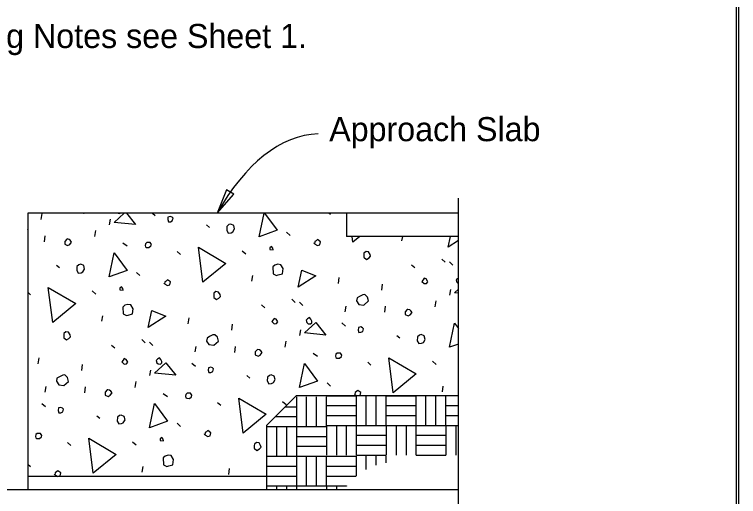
# Model space of a CAD drawing. Extents: x 0 to 30.8, y 0 to 21.2.
# Drawn here: x 26.255 to 30.8, y 6.756 to 9.783 of the extents above; entities that cross this region are included whole.
import ezdxf

# ---------------------------------------------------------------- set-up
doc = ezdxf.new("R2010")
doc.units = 0
for name, color, linetype in [('ActivePts-ConstElements', 7, 'Continuous'), ('Dimension', 7, 'Continuous'), ('Lighting', 7, 'Continuous'), ('Miscellaneous', 7, 'Continuous'), ('Miscellaneous1', 7, 'Continuous'), ('SupstrConc', 7, 'Continuous'), ('TextStructures', 7, 'Continuous')]:
    doc.layers.add(name, color=color, linetype=linetype)

msp = doc.modelspace()

# ---------------------------------------------------------------- linework, layer by layer
at = {"layer": 'ActivePts-ConstElements'}
msp.add_lwpolyline([(0, 0), (30.7879, 0), (30.7879, 19.4596), (0, 19.4596)], close=True, dxfattribs=at)
at = {"layer": 'Dimension'}
msp.add_lwpolyline([(27.5267, 8.5352), (27.6314, 8.6541), (27.5864, 8.682)], close=True, dxfattribs=at)
msp.add_lwpolyline([(29.0415, 6.3424), (29.0415, 8.629)], dxfattribs=at)
msp.add_ellipse((28.2718, 6.6665), major_axis=(0.1111, -2.3674), ratio=0.464296, start_param=3.141604, end_param=3.781059, dxfattribs=at)
at = {"layer": 'Lighting'}
msp.add_line((29.0415, 6.7981), (25.9826, 6.7981), dxfattribs=at)
at = {"layer": 'Miscellaneous'}
for p, q in [((26.4229, 8.4948), (26.4283, 8.5325)), ((27.1206, 8.5353), (27.138, 8.5207)), ((28.2306, 8.5353), (28.2385, 8.5283)), ((29.0415, 8.5353), (28.338, 8.5353)), ((26.8509, 8.4619), (26.857, 8.4972)), ((27.4592, 8.4619), (27.4789, 8.4464)), ((26.7594, 8.3882), (26.7648, 8.4259)), ((27.9633, 8.4158), (27.9843, 8.3955)), ((26.4422, 8.355), (26.4476, 8.3927)), ((28.6871, 8.3612), (28.692, 8.3895)), ((26.9353, 8.35), (26.9611, 8.331)), ((27.2765, 8.2938), (27.2968, 8.276)), ((27.6839, 8.2995), (27.7072, 8.2799)), ((28.9376, 8.2472), (28.9586, 8.2269)), ((28.9864, 8.2292), (29.0074, 8.209)), ((26.5174, 8.2095), (26.5371, 8.1941)), ((28.7478, 8.2119), (28.7681, 8.194)), ((27.0215, 8.1634), (27.0425, 8.1432)), ((27.7453, 8.1089), (27.7514, 8.1442)), ((28.2877, 8.0938), (28.2931, 8.1314)), ((26.7421, 8.0471), (26.7655, 8.0275)), ((28.5601, 8.0529), (28.5655, 8.0905)), ((28.9881, 8.02), (28.9942, 8.0553)), ((26.338, 8.0386), (26.355, 8.0236)), ((27.806, 7.9595), (27.8263, 7.9417)), ((27.9959, 7.9948), (28.0168, 7.9746)), ((28.0447, 7.9769), (28.0656, 7.9566)), ((28.8966, 7.9463), (28.902, 7.984)), ((28.3301, 7.9162), (28.3362, 7.9515)), ((28.5794, 7.9131), (28.5848, 7.9508)), ((26.8035, 7.8565), (26.8096, 7.8918)), ((27.3459, 7.8414), (27.3513, 7.8791)), ((27.6183, 7.8005), (27.6237, 7.8382)), ((28.3101, 7.8461), (28.3334, 7.8265)), ((28.0464, 7.7677), (28.0524, 7.803)), ((27.0541, 7.7425), (27.075, 7.7222)), ((27.9548, 7.694), (27.9603, 7.7317)), ((28.6546, 7.7676), (28.6743, 7.7522)), ((26.8642, 7.7072), (26.8846, 7.6893)), ((27.1029, 7.7245), (27.1238, 7.7043)), ((27.3883, 7.6638), (27.3944, 7.6991)), ((27.6376, 7.6607), (27.643, 7.6984)), ((28.1307, 7.6557), (28.1565, 7.6367)), ((26.4041, 7.5891), (26.4096, 7.6267)), ((27.3683, 7.5938), (27.3917, 7.5741)), ((28.4719, 7.5996), (28.4922, 7.5817)), ((28.8793, 7.6052), (28.9027, 7.5856)), ((26.6765, 7.5482), (26.6819, 7.5858)), ((27.1046, 7.5153), (27.1107, 7.5506)), ((27.7128, 7.5153), (27.7325, 7.4998)), ((27.013, 7.4416), (27.0185, 7.4793)), ((28.2169, 7.4692), (28.2379, 7.4489)), ((26.4465, 7.4115), (26.4526, 7.4468)), ((26.6958, 7.4084), (26.7013, 7.4461)), ((28.9407, 7.4146), (28.9468, 7.4499)), ((27.1889, 7.4034), (27.2147, 7.3844)), ((28.0267, 7.0091), (28.0267, 7.3829)), ((28.088, 7.1966), (28.088, 7.3829)), ((28.1505, 7.1966), (28.1505, 7.3829)), ((28.2128, 7.3895), (28.4016, 7.3895)), ((28.213, 7.1966), (28.213, 7.3829)), ((28.4016, 7.0157), (28.4016, 7.3895)), ((28.4628, 7.2032), (28.4628, 7.3895)), ((28.5253, 7.2032), (28.5253, 7.3895)), ((28.5878, 7.3895), (28.7766, 7.3895)), ((28.5878, 7.2032), (28.5878, 7.3895)), ((28.7766, 7.0157), (28.7766, 7.3895)), ((28.8378, 7.2032), (28.8378, 7.3895)), ((28.9003, 7.2032), (28.9003, 7.3895)), ((28.9628, 7.2032), (28.9628, 7.3895)), ((26.4265, 7.3414), (26.4499, 7.3218)), ((27.5301, 7.3472), (27.5504, 7.3294)), ((27.9375, 7.3529), (27.9609, 7.3333)), ((27.9535, 7.3204), (28.0267, 7.3204)), ((28.2128, 7.327), (28.4016, 7.327)), ((28.5878, 7.327), (28.7766, 7.327)), ((28.9628, 7.327), (29.0415, 7.327)), ((26.7711, 7.2629), (26.7907, 7.2475)), ((27.891, 7.2579), (28.0267, 7.2579)), ((28.2128, 7.2645), (28.4016, 7.2645)), ((28.5878, 7.2645), (28.7766, 7.2645)), ((28.9628, 7.2645), (29.0415, 7.2645)), ((27.2752, 7.2168), (27.2961, 7.1965)), ((27.838, 7.1966), (28.213, 7.1966)), ((27.9005, 7.1966), (27.9005, 7.0091)), ((27.963, 7.1966), (27.963, 7.0091)), ((28.2128, 7.2032), (28.5878, 7.2032)), ((28.2128, 7.2032), (28.2128, 7.0157)), ((28.2753, 7.2032), (28.2753, 7.0157)), ((28.3378, 7.2032), (28.3378, 7.0157)), ((28.5878, 7.2032), (28.9628, 7.2032)), ((28.5878, 7.2032), (28.5878, 7.0157)), ((28.6503, 7.2032), (28.6503, 7.0157)), ((28.7128, 7.2032), (28.7128, 7.0157)), ((28.9628, 7.2033), (29.0415, 7.2033)), ((28.9628, 7.2032), (28.9628, 7.0157)), ((29.0253, 7.2032), (29.0253, 7.0157)), ((28.4016, 7.1407), (28.5878, 7.1407)), ((28.7766, 7.1407), (28.9628, 7.1407)), ((26.5883, 7.0949), (26.6086, 7.077)), ((26.9957, 7.1005), (27.0191, 7.0809)), ((28.0267, 7.1341), (28.213, 7.1341)), ((28.0267, 7.0716), (28.213, 7.0716)), ((28.4016, 7.0782), (28.5878, 7.0782)), ((28.7766, 7.0782), (28.9628, 7.0782)), ((27.838, 7.0091), (28.0267, 7.0091)), ((28.0267, 7.0091), (28.213, 7.0091)), ((28.0267, 6.7981), (28.0267, 7.0091)), ((28.088, 6.8229), (28.088, 7.0091)), ((28.1505, 6.8229), (28.1505, 7.0091)), ((28.213, 7.0091), (28.4017, 7.0091)), ((28.213, 6.8229), (28.213, 7.0091)), ((28.4016, 7.0157), (28.5878, 7.0157)), ((28.4017, 6.8863), (28.4017, 7.0092)), ((28.463, 6.9264), (28.463, 7.0092)), ((28.5255, 6.9529), (28.5255, 7.0092)), ((28.588, 6.9669), (28.588, 7.0092)), ((28.7766, 7.0157), (28.9628, 7.0157)), ((26.338, 6.96), (26.3543, 6.9442)), ((27.0572, 6.9099), (27.0632, 6.9452)), ((27.5996, 6.8948), (27.605, 6.9325)), ((27.838, 6.9466), (28.0267, 6.9466)), ((28.213, 6.9466), (28.4017, 6.9466)), ((27.838, 6.8814), (26.338, 6.8814)), ((27.838, 6.8841), (28.0267, 6.8841)), ((28.213, 6.8842), (28.3991, 6.8842)), ((27.838, 6.8229), (28.213, 6.8229)), ((27.9005, 6.8229), (27.9005, 6.7981)), ((27.963, 6.8229), (27.963, 6.7981)), ((28.213, 6.8229), (28.3388, 6.8229)), ((28.213, 6.8229), (28.213, 6.7981)), ((28.2755, 6.8229), (28.2755, 6.7981)), ((28.338, 6.8229), (28.338, 6.8219))]:
    msp.add_line(p, q, dxfattribs=at)
for points in [[(26.6887, 8.5353), (26.689, 8.535), (26.6923, 8.5353)], [(26.8804, 8.4776), (26.9425, 8.5353)], [(26.957, 8.5353), (27.0134, 8.4641), (26.8804, 8.4776)], [(26.9059, 8.5353), (26.917, 8.534), (26.9186, 8.5353)], [(27.2173, 8.4954), (27.2212, 8.4809), (27.2339, 8.4817), (27.2453, 8.4874), (27.2511, 8.5045), (27.2443, 8.5104), (27.2327, 8.5151), (27.2182, 8.5112), (27.2173, 8.4954)], [(27.7897, 8.3874), (27.8211, 8.5353)], [(27.824, 8.5353), (27.9031, 8.4281), (27.7897, 8.3874)], [(27.5885, 8.4525), (27.5871, 8.4288), (27.5971, 8.4108), (27.6147, 8.4129), (27.6261, 8.4186), (27.6367, 8.437), (27.6309, 8.4587), (27.6131, 8.4669), (27.6011, 8.4636), (27.5885, 8.4525)], [(26.338, 8.424), (26.3403, 8.4261), (26.338, 8.4349)], [(26.5707, 8.3584), (26.5704, 8.3402), (26.5881, 8.332), (26.602, 8.3383), (26.6132, 8.3542), (26.6052, 8.365), (26.5984, 8.371), (26.5874, 8.3732), (26.5826, 8.3719), (26.5707, 8.3584)], [(28.138, 8.3435), (28.1563, 8.3329), (28.1708, 8.3368), (28.1759, 8.3563), (28.1569, 8.3693), (28.1486, 8.3619), (28.1395, 8.3569), (28.138, 8.3435), (28.1367, 8.3483)], [(28.3785, 8.3536), (28.374, 8.3895)], [(28.4221, 8.3895), (28.3785, 8.3536)], [(28.977, 8.3225), (28.9914, 8.3895)], [(29.0415, 8.3639), (28.977, 8.3225)], [(27.0771, 8.3232), (27.0832, 8.3197), (27.099, 8.3188), (27.1115, 8.3299), (27.1144, 8.3384), (27.1057, 8.3516), (27.0851, 8.3513), (27.0767, 8.3438), (27.0745, 8.3329), (27.0771, 8.3232)], [(27.4368, 8.1013), (27.4088, 8.3215), (27.5809, 8.2201), (27.4368, 8.1013)], [(27.8578, 8.3073), (27.879, 8.3052), (27.8765, 8.3149), (27.8684, 8.3256), (27.8576, 8.3176), (27.8578, 8.3073)], [(26.848, 8.135), (26.88, 8.286), (26.9613, 8.1757), (26.848, 8.135)], [(28.4484, 8.2766), (28.4481, 8.2584), (28.4647, 8.2447), (28.4803, 8.2541), (28.4904, 8.2645), (28.4872, 8.2766), (28.4778, 8.2922), (28.4614, 8.2956), (28.4488, 8.2845), (28.4484, 8.2766)], [(26.6467, 8.2002), (26.6453, 8.1765), (26.6553, 8.1585), (26.6729, 8.1606), (26.6843, 8.1662), (26.6949, 8.1846), (26.6891, 8.2063), (26.6714, 8.2145), (26.6593, 8.2113), (26.6467, 8.2002)], [(27.8766, 8.1984), (27.8779, 8.1548), (27.8987, 8.1448), (27.9108, 8.1481), (27.9374, 8.1552), (27.9417, 8.1874), (27.9273, 8.212), (27.9085, 8.2147), (27.8891, 8.2095), (27.8766, 8.1984)], [(28.0352, 8.0701), (28.0583, 8.1772), (28.1456, 8.1411), (28.0352, 8.0701)], [(27.1962, 8.0912), (27.2145, 8.0806), (27.229, 8.0844), (27.2342, 8.1039), (27.2151, 8.1169), (27.2068, 8.1095), (27.1978, 8.1045), (27.1962, 8.0912), (27.1949, 8.096)], [(28.812, 8.1074), (28.8262, 8.0931), (28.8413, 8.0946), (28.8491, 8.1044), (28.8478, 8.1092), (28.8391, 8.1224), (28.8275, 8.1271), (28.8197, 8.1173), (28.812, 8.1074)], [(29.0415, 8.1272), (29.0355, 8.1233), (29.0272, 8.1159), (29.031, 8.1014)], [(29.031, 8.1014), (29.0409, 8.0937), (29.0415, 8.0936)], [(26.495, 7.8489), (26.467, 8.0692), (26.6391, 7.9678), (26.495, 7.8489)], [(26.916, 8.0549), (26.9373, 8.0528), (26.9347, 8.0625), (26.9266, 8.0733), (26.9158, 8.0652), (26.916, 8.0549)], [(29.0176, 8.0357), (29.0415, 8.0579)], [(27.5066, 8.0242), (27.5063, 8.006), (27.5229, 7.9924), (27.5385, 8.0017), (27.5486, 8.0122), (27.5454, 8.0243), (27.536, 8.0399), (27.5196, 8.0432), (27.5071, 8.0321), (27.5066, 8.0242)], [(28.4023, 7.9847), (28.416, 7.9625), (28.4483, 7.9582), (28.4775, 7.9842), (28.4711, 8.0083), (28.4538, 8.0244), (28.4411, 8.0236), (28.4207, 8.0129), (28.405, 8.0036), (28.4023, 7.9847)], [(29.0415, 8.0333), (29.0176, 8.0357)], [(26.9348, 7.9461), (26.9362, 7.9024), (26.9569, 7.8925), (26.969, 7.8957), (26.9956, 7.9028), (26.9999, 7.935), (26.9855, 7.9597), (26.9667, 7.9624), (26.9474, 7.9572), (26.9348, 7.9461)], [(27.0934, 7.8178), (27.1165, 7.9249), (27.2038, 7.8887), (27.0934, 7.8178)], [(28.7079, 7.9165), (28.7076, 7.8983), (28.7253, 7.8901), (28.7392, 7.8964), (28.7504, 7.9123), (28.7424, 7.9231), (28.7356, 7.9291), (28.7246, 7.9313), (28.7198, 7.93), (28.7079, 7.9165)], [(27.8702, 7.8551), (27.8844, 7.8408), (27.8996, 7.8422), (27.9073, 7.8521), (27.906, 7.8569), (27.8973, 7.8701), (27.8857, 7.8747), (27.878, 7.8649), (27.8702, 7.8551)], [(28.0893, 7.8491), (28.0991, 7.8413), (28.1125, 7.8397), (28.1208, 7.8472), (28.1207, 7.8575), (28.115, 7.8689), (28.1069, 7.8797), (28.0937, 7.871), (28.0854, 7.8635), (28.0893, 7.8491)], [(28.0758, 7.7833), (28.1463, 7.8488), (28.2089, 7.7698), (28.0758, 7.7833)], [(28.4127, 7.8011), (28.4166, 7.7866), (28.4293, 7.7875), (28.4407, 7.7931), (28.4465, 7.8102), (28.4397, 7.8161), (28.4281, 7.8208), (28.4136, 7.8169), (28.4127, 7.8011)], [(28.9852, 7.6931), (29.0172, 7.8441), (29.0415, 7.8111)], [(26.5648, 7.7719), (26.5645, 7.7537), (26.5811, 7.74), (26.5967, 7.7494), (26.6068, 7.7598), (26.6036, 7.7719), (26.5943, 7.7875), (26.5778, 7.7909), (26.5653, 7.7798), (26.5648, 7.7719)], [(27.4605, 7.7324), (27.4743, 7.7102), (27.5065, 7.7058), (27.5358, 7.7318), (27.5293, 7.756), (27.512, 7.772), (27.4993, 7.7712), (27.4789, 7.7606), (27.4633, 7.7512), (27.4605, 7.7324)], [(28.7839, 7.7583), (28.7825, 7.7346), (28.7925, 7.7166), (28.8101, 7.7187), (28.8215, 7.7243), (28.8321, 7.7427), (28.8263, 7.7644), (28.8086, 7.7726), (28.7965, 7.7694), (28.7839, 7.7583)], [(29.0415, 7.7134), (28.9852, 7.6931)], [(27.7661, 7.6641), (27.7658, 7.6459), (27.7835, 7.6377), (27.7974, 7.644), (27.8086, 7.66), (27.8006, 7.6708), (27.7938, 7.6767), (27.7829, 7.679), (27.778, 7.6777), (27.7661, 7.6641)], [(28.2725, 7.629), (28.2786, 7.6254), (28.2944, 7.6245), (28.3069, 7.6356), (28.3098, 7.6442), (28.3011, 7.6574), (28.2805, 7.657), (28.2721, 7.6496), (28.2699, 7.6386), (28.2725, 7.629)], [(26.9285, 7.6027), (26.9427, 7.5884), (26.9578, 7.5899), (26.9655, 7.5997), (26.9642, 7.6045), (26.9555, 7.6177), (26.9439, 7.6224), (26.9362, 7.6126), (26.9285, 7.6027)], [(27.134, 7.531), (27.2045, 7.5965), (27.2671, 7.5175), (27.134, 7.531)], [(27.1475, 7.5967), (27.1573, 7.589), (27.1707, 7.5874), (27.1791, 7.5948), (27.1789, 7.6051), (27.1732, 7.6165), (27.1652, 7.6273), (27.152, 7.6186), (27.1436, 7.6112), (27.1475, 7.5967)], [(28.0434, 7.4408), (28.0754, 7.5917), (28.1567, 7.4815), (28.0434, 7.4408)], [(28.6322, 7.407), (28.6042, 7.6273), (28.7763, 7.5259), (28.6322, 7.407)], [(27.4709, 7.5488), (27.4748, 7.5343), (27.4875, 7.5351), (27.4989, 7.5408), (27.5047, 7.5578), (27.4979, 7.5638), (27.4863, 7.5685), (27.4719, 7.5646), (27.4709, 7.5488)], [(26.5188, 7.48), (26.5325, 7.4578), (26.5647, 7.4535), (26.594, 7.4795), (26.5875, 7.5036), (26.5703, 7.5197), (26.5575, 7.5189), (26.5371, 7.5082), (26.5215, 7.4989), (26.5188, 7.48)], [(27.8422, 7.5059), (27.8407, 7.4822), (27.8507, 7.4642), (27.8683, 7.4663), (27.8797, 7.472), (27.8903, 7.4903), (27.8845, 7.5121), (27.8668, 7.5203), (27.8547, 7.517), (27.8422, 7.5059)], [(26.8243, 7.4118), (26.824, 7.3936), (26.8418, 7.3854), (26.8556, 7.3917), (26.8669, 7.4076), (26.8588, 7.4184), (26.852, 7.4244), (26.8411, 7.4266), (26.8362, 7.4253), (26.8243, 7.4118)], [(28.4221, 7.3895), (28.4245, 7.3902), (28.4296, 7.4097), (28.4106, 7.4227), (28.4022, 7.4153), (28.3932, 7.4103), (28.3916, 7.3969), (28.3903, 7.4017)], [(27.3307, 7.3766), (27.3368, 7.3731), (27.3526, 7.3721), (27.3651, 7.3833), (27.368, 7.3918), (27.3593, 7.405), (27.3387, 7.4047), (27.3303, 7.3972), (27.3281, 7.3863), (27.3307, 7.3766)], [(27.6904, 7.1547), (27.6624, 7.3749), (27.8345, 7.2735), (27.6904, 7.1547)], [(28.3916, 7.3969), (28.4043, 7.3895)], [(27.1016, 7.1884), (27.1336, 7.3394), (27.2149, 7.2291), (27.1016, 7.1884)], [(26.5291, 7.2964), (26.533, 7.2819), (26.5457, 7.2828), (26.5572, 7.2884), (26.5629, 7.3055), (26.5562, 7.3114), (26.5446, 7.3161), (26.5301, 7.3122), (26.5291, 7.2964)], [(26.9004, 7.2536), (26.899, 7.2299), (26.909, 7.2119), (26.9265, 7.214), (26.9379, 7.2196), (26.9486, 7.238), (26.9427, 7.2597), (26.925, 7.2679), (26.9129, 7.2647), (26.9004, 7.2536)], [(26.3889, 7.1243), (26.395, 7.1207), (26.4108, 7.1198), (26.4234, 7.1309), (26.4263, 7.1395), (26.4175, 7.1527), (26.3969, 7.1523), (26.3886, 7.1449), (26.3863, 7.1339), (26.3889, 7.1243)], [(27.4498, 7.1446), (27.4682, 7.1339), (27.4827, 7.1378), (27.4878, 7.1573), (27.4688, 7.1703), (27.4604, 7.1629), (27.4514, 7.1579), (27.4498, 7.1446), (27.4485, 7.1494)], [(26.7486, 6.9023), (26.7207, 7.1226), (26.8928, 7.0212), (26.7486, 6.9023)], [(27.1697, 7.1083), (27.1909, 7.1062), (27.1883, 7.1159), (27.1803, 7.1267), (27.1695, 7.1186), (27.1697, 7.1083)], [(27.7602, 7.0776), (27.7599, 7.0594), (27.7765, 7.0457), (27.7921, 7.0551), (27.8023, 7.0656), (27.799, 7.0777), (27.7897, 7.0933), (27.7732, 7.0966), (27.7607, 7.0855), (27.7602, 7.0776)], [(27.1885, 6.9995), (27.1898, 6.9558), (27.2106, 6.9459), (27.2227, 6.9491), (27.2492, 6.9562), (27.2535, 6.9884), (27.2392, 7.0131), (27.2203, 7.0158), (27.201, 7.0106), (27.1885, 6.9995)], [(26.508, 6.8922), (26.5264, 6.8816), (26.5409, 6.8855), (26.546, 6.905), (26.527, 6.918), (26.5186, 6.9106), (26.5096, 6.9056), (26.508, 6.8922), (26.5067, 6.897)]]:
    msp.add_lwpolyline(points, dxfattribs=at)
at = {"layer": 'Miscellaneous1'}
msp.add_lwpolyline([(0, 19.8), (30.8, 19.8), (30.8, 0), (0, 0)], close=True, dxfattribs=at)
at = {"layer": 'SupstrConc'}
for p, q in [((28.338, 8.5353), (26.338, 8.5353)), ((26.338, 8.5353), (26.338, 7.1603)), ((28.338, 8.5353), (28.338, 8.3895)), ((29.0415, 8.3895), (28.338, 8.3895)), ((27.838, 7.2048), (28.0227, 7.3895)), ((29.0415, 7.3895), (28.0227, 7.3895)), ((27.838, 6.7981), (27.838, 7.2048)), ((26.338, 7.1603), (26.338, 6.7981))]:
    msp.add_line(p, q, dxfattribs=at)

# ---------------------------------------------------------------- texts
at = {"layer": 'Dimension'}
msp.add_text('1.  For Box Girder Maintenance Lighting Notes see Sheet 1.', height=0.1512, dxfattribs=at).set_placement((22.7296, 9.5722))
at = {"layer": 'TextStructures'}
msp.add_text('Approach Slab', height=0.1512, dxfattribs=at).set_placement((28.2304, 8.9873))

doc.saveas('drawing.dxf')
